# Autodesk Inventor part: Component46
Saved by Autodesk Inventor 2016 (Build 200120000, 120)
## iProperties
Created: 2016-09
Part Number: Component46
Material: Generic
Document SubType Name: Modeling
Designer: Administrator
Appearance: Generic
Author: Administrator
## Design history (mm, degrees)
feature "Body1"
feature "Body2"
feature "Body4"
feature "Body3"
body "Solid1"
body "Solid2"
body "Solid3"
body "Solid4"
